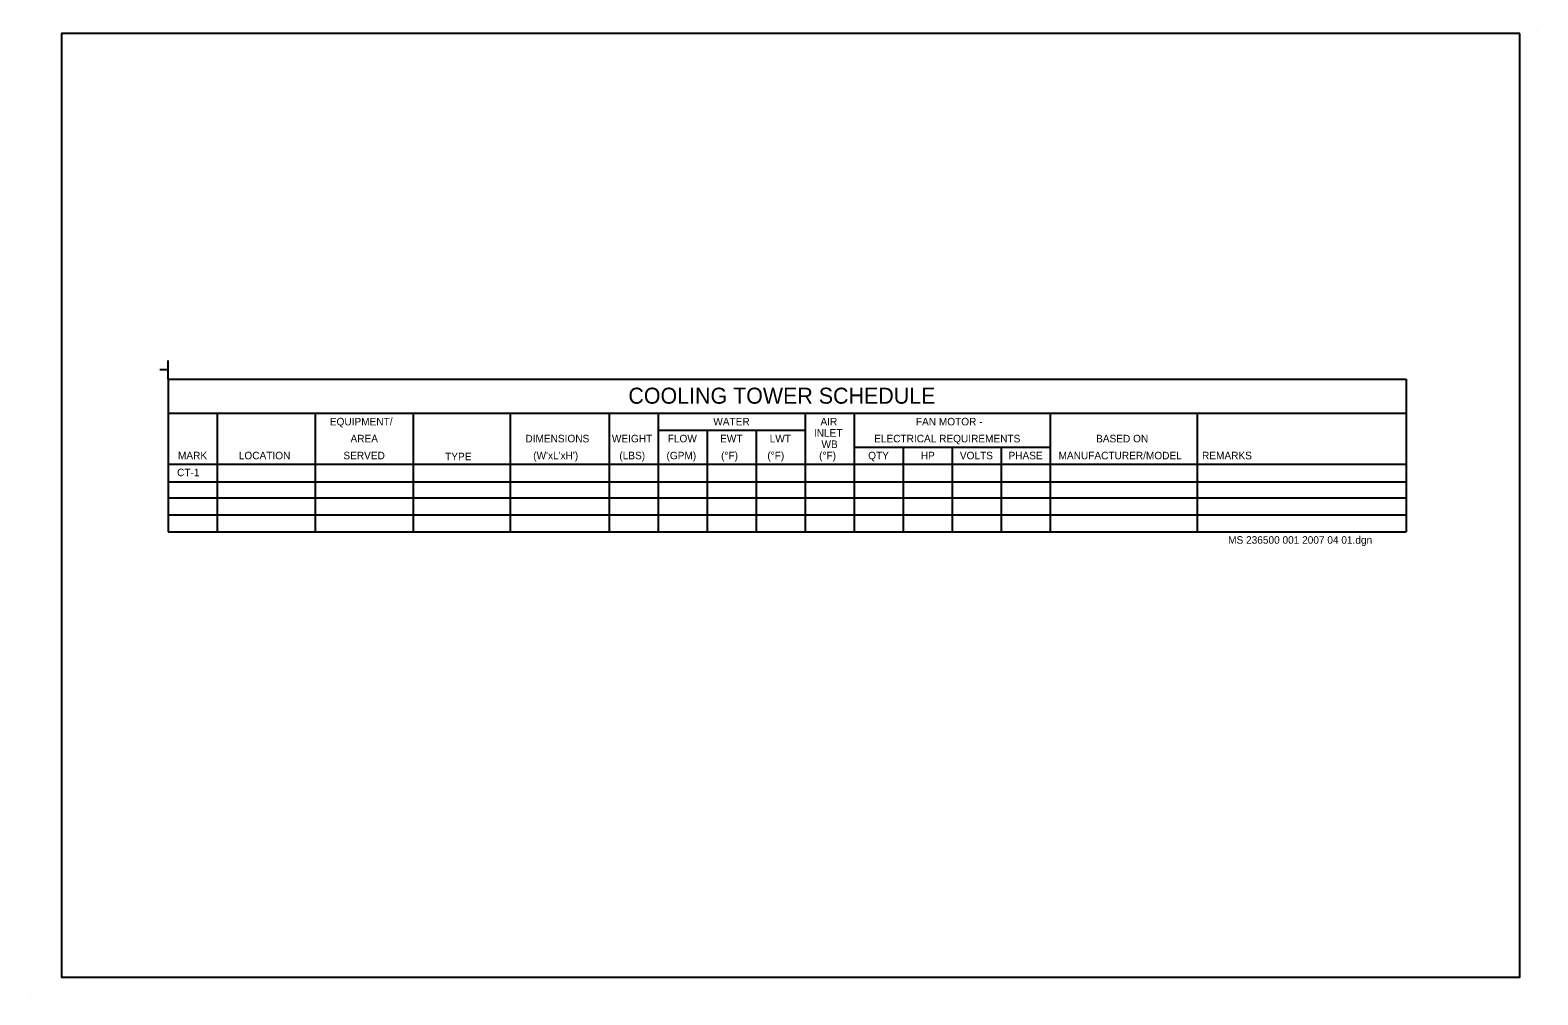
# Model space of a CAD drawing. Extents: x 10013 to 10147, y 10160 to 10245.
import ezdxf

# ---------------------------------------------------------------- set-up
doc = ezdxf.new("R2010")
doc.units = 0
for name, color, linetype in [('Default', 7, 'Continuous'), ('G-ANNO-PD', 7, 'Continuous'), ('G-ANNO-TEXT', 7, 'Continuous'), ('G-DETL-GRID', 7, 'Continuous'), ('G-SCHD-HTXT', 7, 'Continuous'), ('G-SCHD-LINE', 7, 'Continuous'), ('G-SCHD-TEXT', 7, 'Continuous')]:
    doc.layers.add(name, color=color, linetype=linetype)

msp = doc.modelspace()

# ---------------------------------------------------------------- linework, layer by layer
at = {"layer": 'Default'}
for p, q in [((10025.62, 10214.3), (10025.62, 10215.97)), ((10025.62, 10215.14), (10024.87, 10215.14))]:
    msp.add_line(p, q, dxfattribs=at)
at = {"layer": 'G-ANNO-PD'}
for p, q in [((10146.76, 10245.19), (10146.76, 10245.19)), ((10146.76, 10245.19), (10146.76, 10245.19)), ((10013.4, 10159.83), (10013.4, 10159.83)), ((10013.4, 10159.83), (10013.4, 10159.83))]:
    msp.add_line(p, q, dxfattribs=at)
at = {"layer": 'G-DETL-GRID'}
msp.add_lwpolyline([(10145.16, 10244.89), (10016.18, 10244.89), (10016.18, 10161.41), (10145.16, 10161.41)], close=True, dxfattribs=at)
msp.add_lwpolyline([(10145.16, 10244.89), (10016.18, 10244.89), (10016.18, 10161.41), (10145.16, 10161.41)], close=True, dxfattribs=at)
at = {"layer": 'G-SCHD-LINE'}
for p, q in [((10025.62, 10214.3), (10135.12, 10214.3)), ((10025.62, 10214.3), (10025.62, 10200.8)), ((10135.12, 10214.3), (10135.12, 10200.8)), ((10025.62, 10211.3), (10135.12, 10211.3)), ((10029.96, 10211.3), (10029.96, 10206.8)), ((10038.62, 10211.3), (10038.62, 10206.8)), ((10047.29, 10211.3), (10047.29, 10206.8)), ((10055.86, 10211.3), (10055.86, 10200.8)), ((10064.62, 10211.3), (10064.62, 10206.8)), ((10068.96, 10211.3), (10068.96, 10206.8)), ((10081.96, 10211.3), (10081.96, 10206.8)), ((10086.29, 10211.3), (10086.29, 10206.8)), ((10103.62, 10211.3), (10103.62, 10206.8)), ((10116.62, 10211.3), (10116.62, 10206.8)), ((10068.96, 10209.8), (10073.29, 10209.8)), ((10073.29, 10209.8), (10073.29, 10206.8)), ((10073.29, 10209.8), (10077.62, 10209.8)), ((10077.62, 10209.8), (10077.62, 10206.8)), ((10077.62, 10209.8), (10081.96, 10209.8)), ((10086.29, 10208.3), (10090.62, 10208.3)), ((10090.62, 10208.3), (10090.62, 10206.8)), ((10090.62, 10208.3), (10094.96, 10208.3)), ((10094.96, 10208.3), (10094.96, 10206.8)), ((10094.96, 10208.3), (10099.29, 10208.3)), ((10099.29, 10208.3), (10103.62, 10208.3)), ((10099.29, 10208.3), (10099.29, 10206.8)), ((10025.62, 10206.8), (10029.96, 10206.8)), ((10029.96, 10206.8), (10029.96, 10200.8)), ((10029.96, 10206.8), (10034.29, 10206.8)), ((10034.29, 10206.8), (10038.62, 10206.8)), ((10038.62, 10206.8), (10038.62, 10200.8)), ((10038.62, 10206.8), (10042.96, 10206.8)), ((10042.96, 10206.8), (10047.29, 10206.8)), ((10047.29, 10206.8), (10047.29, 10200.8)), ((10047.29, 10206.8), (10051.62, 10206.8)), ((10051.62, 10206.8), (10064.62, 10206.8)), ((10064.62, 10206.8), (10064.62, 10200.8)), ((10064.62, 10206.8), (10068.96, 10206.8)), ((10068.96, 10206.8), (10068.96, 10200.8)), ((10068.96, 10206.8), (10073.29, 10206.8)), ((10073.29, 10206.8), (10073.29, 10200.8)), ((10073.29, 10206.8), (10077.62, 10206.8)), ((10077.62, 10206.8), (10077.62, 10200.8)), ((10077.62, 10206.8), (10081.96, 10206.8)), ((10081.96, 10206.8), (10081.96, 10200.8)), ((10081.96, 10206.8), (10086.29, 10206.8)), ((10086.29, 10206.8), (10086.29, 10200.8)), ((10086.29, 10206.8), (10090.62, 10206.8)), ((10090.62, 10206.8), (10090.62, 10200.8)), ((10090.62, 10206.8), (10094.96, 10206.8)), ((10094.96, 10206.8), (10094.96, 10200.8)), ((10094.96, 10206.8), (10099.29, 10206.8)), ((10099.29, 10206.8), (10103.62, 10206.8)), ((10099.29, 10206.8), (10099.29, 10200.8)), ((10103.62, 10206.8), (10103.62, 10200.8)), ((10103.62, 10206.8), (10107.96, 10206.8)), ((10107.96, 10206.8), (10112.29, 10206.8)), ((10107.96, 10206.8), (10112.29, 10206.8)), ((10112.29, 10206.8), (10116.62, 10206.8)), ((10112.29, 10206.8), (10116.62, 10206.8)), ((10116.62, 10206.8), (10116.62, 10200.8)), ((10116.62, 10206.8), (10135.12, 10206.8)), ((10025.62, 10205.24), (10135.12, 10205.24)), ((10025.62, 10203.8), (10135.12, 10203.8)), ((10025.62, 10202.3), (10135.12, 10202.3)), ((10025.62, 10200.8), (10135.12, 10200.8))]:
    msp.add_line(p, q, dxfattribs=at)

# ---------------------------------------------------------------- texts
at = {"layer": 'G-ANNO-TEXT'}
msp.add_text('MS 236500 001 2007 04 01.dgn ', height=0.6667, dxfattribs=at).set_placement((10119.37, 10199.75))
at = {"layer": 'G-SCHD-HTXT'}
for s, height, p in [('COOLING TOWER SCHEDULE', 1.4167, (10066.32, 10212.14)), ('EQUIPMENT/', 0.667, (10039.91, 10210.22)), ('WATER', 0.667, (10073.83, 10210.22)), ('AIR', 0.667, (10083.31, 10210.22)), ('FAN MOTOR -', 0.6667, (10091.75, 10210.22)), ('AREA', 0.667, (10041.74, 10208.72)), ('DIMENSIONS', 0.667, (10057.21, 10208.72)), ('WEIGHT', 0.667, (10064.86, 10208.72)), ('FLOW', 0.667, (10069.8, 10208.72)), ('EWT', 0.667, (10074.43, 10208.72)), ('LWT', 0.667, (10078.82, 10208.72)), ('INLET', 0.667, (10082.73, 10209.22)), ('WB', 0.667, (10083.4, 10208.22)), ('ELECTRICAL REQUIREMENTS', 0.6667, (10088.06, 10208.72)), ('BASED ON', 0.667, (10107.69, 10208.72)), ('MARK', 0.667, (10026.48, 10207.22)), ('LOCATION', 0.667, (10031.86, 10207.22)), ('SERVED', 0.667, (10041.11, 10207.22)), ('TYPE', 0.667, (10050.11, 10207.13)), ("(W'xL'xH')", 0.667, (10057.9, 10207.22)), ('(LBS)', 0.667, (10065.52, 10207.22)), ('(GPM)', 0.667, (10069.69, 10207.22)), ('(°F)', 0.667, (10074.52, 10207.22)), ('(°F)', 0.667, (10078.61, 10207.22)), ('(°F)', 0.667, (10083.19, 10207.22)), ('QTY', 0.667, (10087.53, 10207.22)), ('HP', 0.667, (10092.18, 10207.22)), ('VOLTS', 0.667, (10095.64, 10207.22)), ('PHASE', 0.667, (10099.94, 10207.22)), ('MANUFACTURER/MODEL', 0.6667, (10104.37, 10207.22)), ('REMARKS', 0.667, (10117.06, 10207.22))]:
    msp.add_text(s, height=height, dxfattribs=at).set_placement(p)
at = {"layer": 'G-SCHD-TEXT'}
msp.add_text('CT-1', height=0.667, dxfattribs=at).set_placement((10026.4, 10205.72))

doc.saveas('drawing.dxf')
